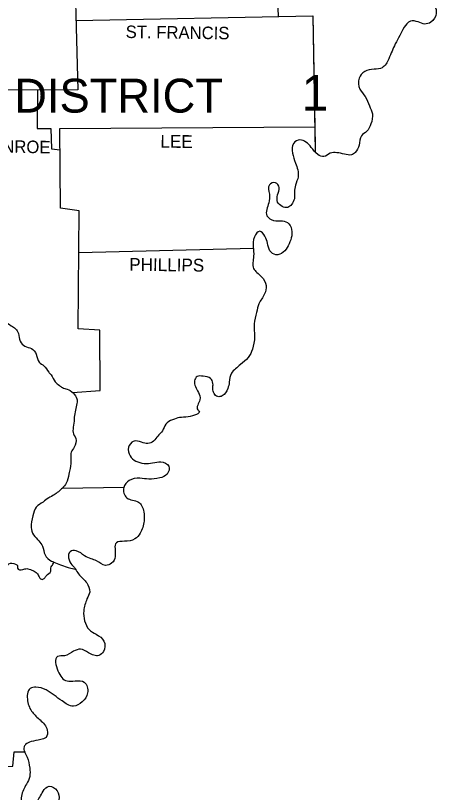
# Model space of a CAD drawing. Extents: x 1373878 to 1386598, y 1168333 to 1170533.
# Drawn here: x 1376719.5 to 1376861.3, y 1169816.7 to 1170078.1 of the extents above; entities that cross this region are included whole.
import ezdxf

# ---------------------------------------------------------------- set-up
doc = ezdxf.new("R2010")
doc.units = 0
doc.layers.add('1', color=7, linetype='Continuous')
doc.layers.add('Default', color=7, linetype='Continuous')

msp = doc.modelspace()

# ---------------------------------------------------------------- linework, layer by layer
at = {"layer": '1'}
msp.add_lwpolyline([(1376732.39, 1169894.21), (1376734.63, 1169893.34), (1376737.2, 1169892.44), (1376739.64, 1169891.82)], dxfattribs=at)
for points in [[(1376856.89, 1170115.51), (1376857.29, 1170112.61), (1376855.59, 1170109.51), (1376854.99, 1170106.41), (1376855.29, 1170103.31), (1376852.09, 1170101.61), (1376849.29, 1170099.61), (1376850.89, 1170097.21), (1376853.89, 1170095.01), (1376856.89, 1170093.31), (1376858.79, 1170091.61), (1376859.29, 1170087.51), (1376859.79, 1170084.91), (1376860.79, 1170081.31), (1376861.19, 1170078.81), (1376859.39, 1170075.81), (1376857.29, 1170075.21), (1376855.09, 1170075.91), (1376852.49, 1170076.11), (1376850.39, 1170074.11), (1376848.89, 1170071.31), (1376847.39, 1170068.51), (1376846.29, 1170066.11), (1376845.19, 1170063.51), (1376842.99, 1170060.51), (1376840.29, 1170060.01), (1376837.09, 1170059.21), (1376835.19, 1170057.01), (1376835.49, 1170053.31), (1376837.29, 1170050.81), (1376838.69, 1170047.71), (1376839.69, 1170045.01), (1376839.19, 1170041.61), (1376837.79, 1170039.11), (1376835.99, 1170037.61), (1376835.19, 1170034.41), (1376833.89, 1170032.01), (1376832.69, 1170031.21), (1376830.29, 1170031.41), (1376827.69, 1170031.91), (1376825.49, 1170031.71), (1376823.39, 1170030.61), (1376821.29, 1170031.31), (1376819.09, 1170033.71), (1376817.29, 1170035.51), (1376815.29, 1170036.21), (1376813.19, 1170035.11), (1376812.79, 1170031.81), (1376813.79, 1170028.41), (1376814.69, 1170023.81), (1376813.79, 1170021.01), (1376813.49, 1170016.41)], [(1376813.49, 1170016.41), (1376811.19, 1170013.51), (1376807.79, 1170015.31), (1376807.79, 1170017.71), (1376808.29, 1170020.21), (1376807.09, 1170021.81), (1376804.99, 1170021.11), (1376804.99, 1170018.01), (1376804.79, 1170015.01), (1376804.19, 1170010.71), (1376805.59, 1170009.41), (1376808.79, 1170009.01), (1376811.09, 1170008.41), (1376812.49, 1170006.11), (1376812.39, 1170003.31), (1376811.29, 1170000.61), (1376809.69, 1169998.41), (1376807.19, 1169997.61), (1376805.19, 1169998.91), (1376804.39, 1170001.51), (1376803.49, 1170003.81), (1376801.79, 1170005.51), (1376799.99, 1170003.61), (1376799.59, 1170000.11), (1376799.69, 1169997.11), (1376799.69, 1169993.01), (1376802.29, 1169990.31), (1376803.89, 1169987.21), (1376803.39, 1169984.41), (1376801.49, 1169981.11), (1376800.69, 1169978.21), (1376799.89, 1169974.31), (1376799.99, 1169970.01), (1376799.29, 1169965.81), (1376797.89, 1169963.01), (1376795.29, 1169960.71), (1376793.59, 1169959.21), (1376792.19, 1169957.71), (1376791.49, 1169954.71), (1376790.99, 1169952.61), (1376789.09, 1169950.11), (1376787.59, 1169949.91), (1376786.39, 1169950.91), (1376785.99, 1169952.61), (1376785.99, 1169954.31), (1376785.19, 1169956.01), (1376782.69, 1169956.71), (1376780.69, 1169956.61), (1376779.79, 1169955.21), (1376781.09, 1169951.31), (1376781.59, 1169948.81), (1376780.89, 1169945.41), (1376781.29, 1169945.01), (1376777.69, 1169943.11), (1376774.79, 1169942.81), (1376772.39, 1169942.11), (1376770.09, 1169940.61), (1376768.99, 1169938.41), (1376767.39, 1169936.61), (1376765.99, 1169934.91), (1376764.09, 1169934.11), (1376761.99, 1169934.51), (1376759.19, 1169934.81), (1376757.59, 1169932.81), (1376758.09, 1169929.91), (1376759.99, 1169928.21), (1376762.79, 1169927.41), (1376765.69, 1169927.61), (1376768.49, 1169927.91), (1376771.09, 1169926.51), (1376770.59, 1169923.81), (1376768.09, 1169922.51), (1376764.39, 1169922.11), (1376761.39, 1169922.41), (1376757.79, 1169921.61), (1376755.99, 1169919.31), (1376756.99, 1169915.81), (1376760.89, 1169914.41), (1376762.69, 1169911.11), (1376762.79, 1169908.01), (1376761.49, 1169903.91), (1376759.69, 1169902.01), (1376756.19, 1169901.21), (1376753.49, 1169900.71), (1376753.09, 1169896.11), (1376751.89, 1169893.81), (1376749.79, 1169893.11), (1376746.79, 1169894.61), (1376744.99, 1169895.31), (1376742.79, 1169896.31), (1376739.99, 1169898.01), (1376737.89, 1169897.71), (1376738.49, 1169893.31), (1376738.69, 1169893.11), (1376741.09, 1169889.81), (1376743.49, 1169887.21), (1376744.59, 1169884.11)], [(1376709.89, 1169984.21), (1376710.19, 1169980.11), (1376712.59, 1169979.51), (1376713.59, 1169978.41), (1376714.09, 1169976.11), (1376715.79, 1169975.11), (1376718.09, 1169973.71), (1376719.49, 1169972.71), (1376720.49, 1169971.11), (1376721.09, 1169968.51), (1376722.69, 1169966.81), (1376724.89, 1169966.01), (1376726.49, 1169964.11), (1376727.49, 1169961.41), (1376729.09, 1169960.21), (1376730.69, 1169958.11), (1376731.49, 1169957.21), (1376732.89, 1169954.81), (1376734.29, 1169953.61), (1376735.29, 1169952.91), (1376736.89, 1169952.41), (1376738.89, 1169951.11), (1376740.19, 1169949.11), (1376740.19, 1169947.61), (1376739.69, 1169945.31), (1376739.29, 1169942.91), (1376739.09, 1169940.21), (1376738.89, 1169937.81), (1376739.79, 1169935.81), (1376739.29, 1169932.81), (1376738.29, 1169931.21), (1376738.19, 1169929.01), (1376737.89, 1169925.71), (1376737.49, 1169923.81), (1376736.59, 1169920.71), (1376735.29, 1169919.11)], [(1376735.29, 1169919.11), (1376732.49, 1169916.81), (1376730.69, 1169915.81), (1376728.79, 1169914.41), (1376726.49, 1169912.71), (1376725.39, 1169909.81), (1376724.79, 1169905.81), (1376725.59, 1169903.41), (1376727.39, 1169901.31), (1376728.59, 1169899.61), (1376729.49, 1169896.61), (1376731.69, 1169894.51), (1376732.39, 1169894.21)], [(1376744.59, 1169884.11), (1376743.59, 1169881.81), (1376742.49, 1169877.81), (1376742.79, 1169874.41), (1376744.29, 1169871.51), (1376746.69, 1169869.91), (1376749.29, 1169867.61), (1376749.09, 1169864.11), (1376747.59, 1169862.81), (1376744.09, 1169863.71), (1376741.39, 1169864.91), (1376739.09, 1169864.21), (1376735.99, 1169862.71), (1376733.69, 1169862.41), (1376733.79, 1169857.61), (1376736.89, 1169854.21), (1376739.59, 1169854.21), (1376742.69, 1169853.81), (1376743.79, 1169850.21), (1376741.99, 1169847.21), (1376738.99, 1169845.71), (1376735.19, 1169847.51), (1376732.49, 1169849.41), (1376729.79, 1169851.21), (1376726.39, 1169852.11), (1376724.49, 1169851.71), (1376723.59, 1169847.51), (1376725.19, 1169843.71), (1376727.79, 1169841.11), (1376730.19, 1169837.71), (1376729.79, 1169835.21), (1376727.99, 1169834.51), (1376724.79, 1169833.81), (1376722.89, 1169832.81), (1376722.39, 1169832.01), (1376723.39, 1169828.61), (1376724.29, 1169824.91), (1376724.29, 1169822.11), (1376723.19, 1169819.51), (1376721.49, 1169815.51), (1376721.69, 1169812.91), (1376722.89, 1169811.71), (1376724.39, 1169812.11), (1376726.39, 1169813.51), (1376727.69, 1169815.11), (1376728.79, 1169817.11), (1376730.89, 1169818.81), (1376733.49, 1169817.31), (1376734.09, 1169814.21), (1376732.59, 1169811.51), (1376730.49, 1169810.31), (1376727.89, 1169809.31), (1376725.99, 1169807.11), (1376726.49, 1169804.51), (1376727.99, 1169803.11), (1376731.69, 1169803.81), (1376734.19, 1169804.91), (1376735.59, 1169806.31), (1376737.29, 1169808.01), (1376738.19, 1169809.71), (1376739.49, 1169811.51), (1376741.79, 1169812.01), (1376742.89, 1169810.51), (1376742.49, 1169807.11), (1376741.09, 1169803.91), (1376739.19, 1169801.21), (1376737.09, 1169799.31), (1376734.49, 1169795.21), (1376734.99, 1169791.41), (1376735.99, 1169788.31), (1376737.39, 1169785.91), (1376739.79, 1169786.41), (1376742.49, 1169786.71), (1376744.09, 1169785.41), (1376743.89, 1169782.62), (1376741.89, 1169779.92), (1376739.99, 1169777.32), (1376738.99, 1169773.72), (1376739.39, 1169771.22), (1376739.39, 1169768.92), (1376738.59, 1169766.42), (1376737.19, 1169765.02), (1376733.49, 1169765.12), (1376729.59, 1169765.52), (1376727.49, 1169764.32), (1376727.89, 1169760.92), (1376730.19, 1169758.42), (1376731.79, 1169757.12), (1376734.09, 1169754.32), (1376735.09, 1169752.02), (1376734.79, 1169750.02), (1376733.39, 1169748.32), (1376729.29, 1169746.32)]]:
    msp.add_spline(points, degree=3, dxfattribs=at)
at = {"layer": 'Default'}
msp.add_line((1376735.29, 1169919.12), (1376756.04, 1169919.43), dxfattribs=at)
for points in [[(1376806.29, 1170122.79), (1376806.79, 1170083.91), (1376807.69, 1170083.31), (1376808.01, 1170077.77)], [(1376738.99, 1170107.91), (1376740.49, 1170053.11), (1376716.69, 1170053.01), (1376716.59, 1170050.81), (1376709.69, 1170050.41), (1376709.09, 1170039.01), (1376699.61, 1170039.01)], [(1376739.86, 1170076.4), (1376819.59, 1170078.01)], [(1376819.59, 1170078.01), (1376820.39, 1170034.21)], [(1376819.59, 1170078.01), (1376820.39, 1170034.21)], [(1376819.59, 1170078.01), (1376820.39, 1170034.21)], [(1376819.59, 1170078.01), (1376820.39, 1170034.21)], [(1376819.59, 1170078.01), (1376820.39, 1170034.21)], [(1376819.59, 1170078.01), (1376820.39, 1170034.21)], [(1376819.59, 1170078.01), (1376820.39, 1170034.21)], [(1376819.59, 1170078.01), (1376820.43, 1170032.2)], [(1376726.9, 1170053.05), (1376726.79, 1170040.11), (1376731.39, 1170040.11), (1376731.59, 1170033.21), (1376734.55, 1170032.9)], [(1376738.66, 1169951.31), (1376747.99, 1169951.91), (1376747.89, 1169972.21), (1376740.59, 1169972.71), (1376740.99, 1170012.41), (1376734.69, 1170013.31), (1376734.49, 1170040.01), (1376820.28, 1170040.61)], [(1376740.85, 1169998.3), (1376799.61, 1169999.76)], [(1376691.99, 1169831.74), (1376705.89, 1169830.91), (1376706.49, 1169825.11), (1376718.59, 1169825.51), (1376719.09, 1169830.41), (1376722.83, 1169830.41)]]:
    msp.add_lwpolyline(points, dxfattribs=at)
msp.add_spline([(1376671.89, 1169932.51), (1376673.39, 1169931.51), (1376675.49, 1169931.61), (1376676.89, 1169932.21), (1376677.99, 1169932.11), (1376679.49, 1169931.21), (1376680.49, 1169930.01), (1376681.19, 1169929.11), (1376681.69, 1169927.71), (1376681.69, 1169926.41), (1376682.19, 1169924.61), (1376682.79, 1169923.91), (1376683.59, 1169922.61), (1376684.09, 1169921.41), (1376684.39, 1169920.61), (1376685.49, 1169919.31), (1376686.49, 1169919.41), (1376687.39, 1169919.31), (1376688.59, 1169918.61), (1376690.39, 1169917.21), (1376690.69, 1169916.81), (1376691.89, 1169914.21), (1376692.09, 1169912.61), (1376692.29, 1169910.51), (1376692.69, 1169908.51), (1376693.49, 1169906.31), (1376693.89, 1169904.81), (1376694.79, 1169902.71), (1376695.39, 1169901.31), (1376696.19, 1169899.51), (1376697.39, 1169897.51), (1376697.89, 1169896.31), (1376699.59, 1169896.41), (1376700.79, 1169896.91), (1376701.69, 1169897.71), (1376702.79, 1169897.61), (1376703.99, 1169897.21), (1376705.59, 1169896.91), (1376706.59, 1169897.51), (1376707.09, 1169897.91), (1376707.19, 1169898.81), (1376708.09, 1169899.31), (1376709.09, 1169898.61), (1376710.19, 1169897.01), (1376710.19, 1169896.01), (1376709.79, 1169895.41), (1376708.49, 1169894.61), (1376706.69, 1169894.01), (1376706.19, 1169893.31), (1376707.89, 1169892.51), (1376710.59, 1169892.31), (1376711.29, 1169892.91), (1376713.09, 1169892.41), (1376713.79, 1169892.91), (1376716.19, 1169892.81), (1376717.29, 1169893.61), (1376719.49, 1169893.51), (1376720.19, 1169893.01), (1376720.19, 1169892.11), (1376721.99, 1169891.71), (1376723.29, 1169892.01), (1376724.99, 1169891.51), (1376726.49, 1169890.71), (1376727.29, 1169889.61), (1376728.29, 1169888.41), (1376729.19, 1169888.71), (1376729.89, 1169889.61), (1376731.39, 1169891.21), (1376731.39, 1169892.21), (1376731.79, 1169892.91), (1376732.39, 1169894.21)], degree=3, dxfattribs=at)

# ---------------------------------------------------------------- texts
for s, height, rotation, p in [('ST. FRANCIS', 4.1992, 359.2216, (1376756.59, 1170070.51)), ('MONROE', 4.199, 359.0331, (1376705.99, 1170032.11)), ('LEE', 4.301, 359.4327, (1376768.29, 1170033.61)), ('PHILLIPS', 4.299, 359.318, (1376757.79, 1169992.21))]:
    msp.add_text(s, height=height, rotation=rotation, dxfattribs=at).set_placement(p)
for s, height, p in [('DISTRICT', 11.4, (1376719.09, 1170045.41)), ('1', 12, (1376815.89, 1170046.11))]:
    msp.add_text(s, height=height, dxfattribs=at).set_placement(p)

doc.saveas('drawing.dxf')
